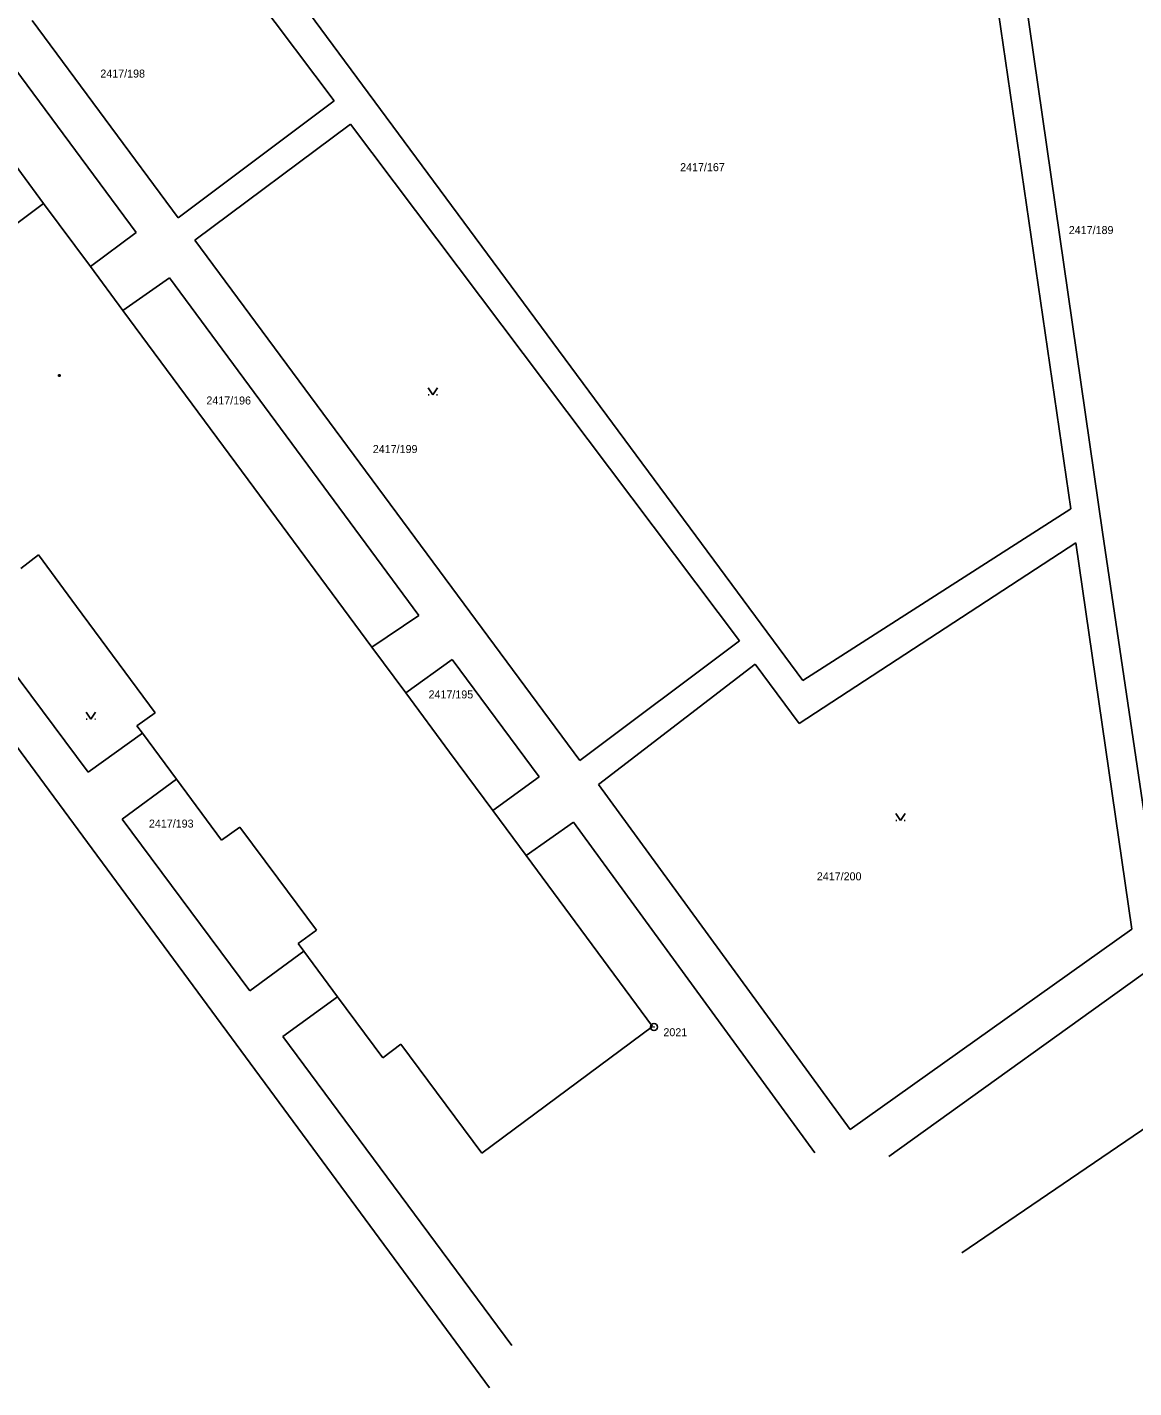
# Model space of a CAD drawing. Extents: x -609709 to -609357, y -1051535 to -1051131.
# Drawn here: x -609542.7 to -609483.9, y -1051503.8 to -1051431.5 of the extents above; entities that cross this region are included whole.
import ezdxf

# ---------------------------------------------------------------- set-up
doc = ezdxf.new("R2010")
doc.units = 0
doc.layers.add('Vrstva 10', color=7, linetype='Continuous')

msp = doc.modelspace()

# ---------------------------------------------------------------- linework, layer by layer
at = {"layer": 'Vrstva 10'}
for p, q in [((-609494.29, -1051397.81), (-609485.56, -1051458.32)), ((-609494.35, -1051408.39), (-609487.25, -1051457.08)), ((-609532.43, -1051424.35), (-609501.47, -1051466.19)), ((-609534.3, -1051424.88), (-609526.36, -1051435.41)), ((-609546.08, -1051429.98), (-609536.87, -1051442.41)), ((-609542.4, -1051431.15), (-609534.64, -1051441.62)), ((-609548.51, -1051431.78), (-609541.79, -1051440.87)), ((-609534.64, -1051441.62), (-609526.36, -1051435.41)), ((-609533.77, -1051442.81), (-609525.5, -1051436.65)), ((-609525.5, -1051436.65), (-609504.83, -1051464.09)), ((-609550.88, -1051447.62), (-609541.79, -1051440.87)), ((-609541.79, -1051440.87), (-609539.31, -1051444.22)), ((-609539.31, -1051444.22), (-609536.87, -1051442.41)), ((-609533.77, -1051442.81), (-609513.32, -1051470.44)), ((-609562.01, -1051444.23), (-609518.11, -1051503.76)), ((-609539.31, -1051444.22), (-609537.59, -1051446.55)), ((-609537.59, -1051446.55), (-609535.1, -1051444.82)), ((-609535.1, -1051444.82), (-609521.86, -1051462.74)), ((-609537.59, -1051446.55), (-609530.93, -1051455.55)), ((-609540.995, -1051449.965), (-609540.92, -1051449.965)), ((-609540.995, -1051450.04), (-609540.995, -1051449.965)), ((-609540.92, -1051450.04), (-609540.995, -1051450.04)), ((-609540.92, -1051449.965), (-609540.92, -1051450.04)), ((-609521.37, -1051450.655), (-609521.12, -1051451.03)), ((-609521.37, -1051451.03), (-609521.32, -1051451.03)), ((-609521.12, -1051451.03), (-609520.87, -1051450.655)), ((-609520.92, -1051451.03), (-609520.87, -1051451.03)), ((-609530.93, -1051455.55), (-609524.37, -1051464.42)), ((-609501.47, -1051466.19), (-609487.25, -1051457.08)), ((-609485.56, -1051458.32), (-609482.58, -1051478.39)), ((-609548.38, -1051459.06), (-609539.42, -1051471.07)), ((-609501.67, -1051468.48), (-609486.98, -1051458.88)), ((-609486.98, -1051458.88), (-609484, -1051479.4)), ((-609543.01, -1051460.25), (-609542.07, -1051459.52)), ((-609542.07, -1051459.52), (-609540.04, -1051462.26)), ((-609540.04, -1051462.26), (-609535.86, -1051467.91)), ((-609524.37, -1051464.42), (-609521.86, -1051462.74)), ((-609513.32, -1051470.44), (-609504.83, -1051464.09)), ((-609524.37, -1051464.42), (-609522.56, -1051466.86)), ((-609522.56, -1051466.86), (-609520.1, -1051465.09)), ((-609520.1, -1051465.09), (-609515.47, -1051471.31)), ((-609512.32, -1051471.72), (-609504.01, -1051465.33)), ((-609504.01, -1051465.33), (-609501.67, -1051468.48)), ((-609522.56, -1051466.86), (-609520.23, -1051470.01)), ((-609539.53, -1051467.885), (-609539.28, -1051468.26)), ((-609539.53, -1051468.26), (-609539.48, -1051468.26)), ((-609539.28, -1051468.26), (-609539.03, -1051467.885)), ((-609539.08, -1051468.26), (-609539.03, -1051468.26)), ((-609536.84, -1051468.61), (-609535.86, -1051467.91)), ((-609539.42, -1051471.07), (-609536.55, -1051468.99)), ((-609536.84, -1051468.61), (-609536.55, -1051468.99)), ((-609536.55, -1051468.99), (-609534.74, -1051471.44)), ((-609520.23, -1051470.01), (-609517.94, -1051473.11)), ((-609517.94, -1051473.11), (-609515.47, -1051471.31)), ((-609537.63, -1051473.57), (-609534.74, -1051471.44)), ((-609534.74, -1051471.44), (-609532.35, -1051474.68)), ((-609512.32, -1051471.72), (-609498.97, -1051490.05)), ((-609517.94, -1051473.11), (-609516.17, -1051475.5)), ((-609496.54, -1051473.255), (-609496.29, -1051473.63)), ((-609496.29, -1051473.63), (-609496.04, -1051473.255)), ((-609537.63, -1051473.57), (-609530.85, -1051482.68)), ((-609532.35, -1051474.68), (-609531.37, -1051473.98)), ((-609531.37, -1051473.98), (-609529.35, -1051476.7)), ((-609516.17, -1051475.5), (-609513.65, -1051473.72)), ((-609513.65, -1051473.72), (-609500.83, -1051491.29)), ((-609496.54, -1051473.63), (-609496.49, -1051473.63)), ((-609496.09, -1051473.63), (-609496.04, -1051473.63)), ((-609516.17, -1051475.5), (-609509.46, -1051484.58)), ((-609529.35, -1051476.7), (-609527.31, -1051479.45)), ((-609496.9, -1051491.48), (-609476.45, -1051476.77)), ((-609528.28, -1051480.17), (-609527.31, -1051479.45)), ((-609498.97, -1051490.05), (-609484, -1051479.4)), ((-609530.85, -1051482.68), (-609527.98, -1051480.57)), ((-609528.28, -1051480.17), (-609527.98, -1051480.57)), ((-609527.98, -1051480.57), (-609526.18, -1051483)), ((-609493.03, -1051496.59), (-609470.48, -1051481.24)), ((-609529.09, -1051485.11), (-609526.18, -1051483)), ((-609526.18, -1051483), (-609523.78, -1051486.23)), ((-609518.53, -1051491.3), (-609509.46, -1051484.58)), ((-609529.09, -1051485.11), (-609516.93, -1051501.52)), ((-609523.78, -1051486.23), (-609522.82, -1051485.52)), ((-609522.82, -1051485.52), (-609518.53, -1051491.3))]:
    msp.add_line(p, q, dxfattribs=at)
for radius in [0.188, 0.0025]:
    msp.add_circle((-609509.38, -1051484.6), radius, dxfattribs=at)

# ---------------------------------------------------------------- texts
for s, p in [('2417/198', (-609538.78, -1051434.18)), ('2417/167', (-609507.99, -1051439.15)), ('2417/189', (-609487.35, -1051442.49)), ('2417/196', (-609533.15, -1051451.54)), ('2417/199', (-609524.31, -1051454.12)), ('2417/195', (-609521.35, -1051467.15)), ('2417/193', (-609536.2, -1051474.01)), ('2417/200', (-609500.73, -1051476.81)), ('2021', (-609508.879, -1051485.09))]:
    msp.add_text(s, height=0.425, dxfattribs=at).set_placement(p)

doc.saveas('drawing.dxf')
